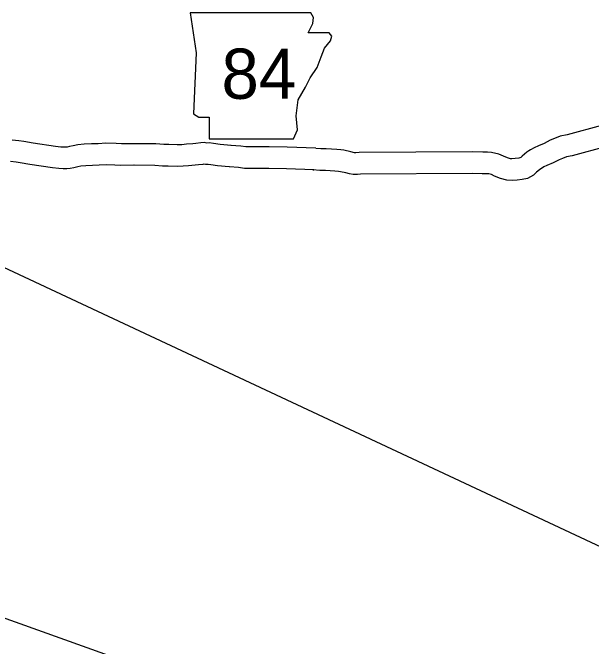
# Model space of a CAD drawing. Extents: x 1373862 to 1377080, y 1164775 to 1170415.
# Drawn here: x 1374204.1 to 1374284.4, y 1170151.1 to 1170239 of the extents above; entities that cross this region are included whole.
import ezdxf

# ---------------------------------------------------------------- set-up
doc = ezdxf.new("R2010")
doc.units = 0
doc.layers.add('1', color=7, linetype='Continuous')
doc.layers.add('Default', color=7, linetype='Continuous')

msp = doc.modelspace()

# ---------------------------------------------------------------- linework, layer by layer
at = {"layer": '1'}
for p in [(1374155.089, 1170226.036), (1374172.843, 1170165.768)]:
    msp.add_line(p, (1374640.758, 1169998.763), dxfattribs=at)
at = {"layer": 'Default'}
msp.add_lwpolyline([(1374228.721, 1170239.039), (1374229.559, 1170233.456), (1374229.186, 1170224.988), (1374229.931, 1170224.523), (1374231.327, 1170224.523), (1374231.327, 1170221.545), (1374243.051, 1170221.545), (1374243.609, 1170222.755), (1374243.423, 1170224.709), (1374243.702, 1170226.942), (1374244.725, 1170228.71), (1374245.377, 1170230.013), (1374246.307, 1170231.409), (1374246.866, 1170232.897), (1374247.331, 1170234.107), (1374248.168, 1170235.13), (1374248.354, 1170235.782), (1374247.982, 1170236.247), (1374245.098, 1170236.247), (1374245.749, 1170237.55), (1374245.842, 1170238.387), (1374245.456, 1170239.03)], close=True, dxfattribs=at)
for points in [[(1374285.752, 1170223.374), (1374281.025, 1170222.103), (1374280.056, 1170221.897), (1374279.255, 1170221.581), (1374278.653, 1170221.336), (1374277.813, 1170220.895), (1374277.029, 1170220.568), (1374276.41, 1170220.299), (1374275.925, 1170220.007), (1374275.712, 1170219.849), (1374275.414, 1170219.672), (1374274.767, 1170219.126), (1374274.567, 1170218.935), (1374274.46, 1170218.875), (1374274.293, 1170218.841), (1374273.808, 1170218.786), (1374273.346, 1170218.75), (1374273.144, 1170218.762), (1374272.747, 1170218.87), (1374272.156, 1170219.114), (1374271.525, 1170219.411), (1374270.513, 1170219.647), (1374269.947, 1170219.656), (1374269.312, 1170219.67), (1374267.893, 1170219.718), (1374252.159, 1170219.623), (1374251.706, 1170219.577), (1374251.605, 1170219.573), (1374251.51, 1170219.593), (1374250.992, 1170219.728), (1374250.05, 1170219.935), (1374249.606, 1170219.981), (1374249.067, 1170220.037), (1374248.306, 1170220.105), (1374247.564, 1170220.131), (1374246.858, 1170220.134), (1374246.152, 1170220.2)], [(1374220.886, 1170220.857), (1374219.194, 1170220.814), (1374218.442, 1170220.882), (1374216.999, 1170220.935), (1374215.93, 1170220.852), (1374215.035, 1170220.834), (1374214.008, 1170220.772), (1374213.121, 1170220.696), (1374212.473, 1170220.56), (1374211.992, 1170220.451), (1374211.656, 1170220.393), (1374211.42, 1170220.37), (1374211.122, 1170220.36), (1374210.747, 1170220.379), (1374210.041, 1170220.472), (1374206.93, 1170220.94), (1374205.634, 1170221.156), (1374204.962, 1170221.27), (1374204.011, 1170221.359)], [(1374234.401, 1170220.612), (1374232.857, 1170220.765), (1374231.948, 1170220.886), (1374231.353, 1170220.953), (1374231.042, 1170220.95), (1374230.675, 1170221.001), (1374230.205, 1170220.98), (1374229.501, 1170220.897), (1374229.074, 1170220.845), (1374228.205, 1170220.77), (1374227.534, 1170220.715), (1374226.904, 1170220.674), (1374225.757, 1170220.73), (1374225.041, 1170220.743), (1374223.952, 1170220.844), (1374220.931, 1170220.857)], [(1374246.152, 1170220.214), (1374242.151, 1170220.35), (1374239.667, 1170220.429), (1374238.089, 1170220.424), (1374236.455, 1170220.409), (1374235.751, 1170220.523), (1374234.352, 1170220.616)], [(1374286.479, 1170220.463), (1374281.727, 1170219.185), (1374280.923, 1170219.014), (1374280.371, 1170218.797), (1374279.919, 1170218.612), (1374279.09, 1170218.177), (1374278.204, 1170217.808), (1374277.788, 1170217.627), (1374277.598, 1170217.512), (1374277.375, 1170217.347), (1374277.157, 1170217.218), (1374276.774, 1170216.894), (1374276.36, 1170216.499), (1374275.514, 1170216.029), (1374274.765, 1170215.875), (1374274.092, 1170215.799), (1374273.378, 1170215.744), (1374272.661, 1170215.784), (1374271.777, 1170216.025), (1374270.944, 1170216.368), (1374270.533, 1170216.562), (1374270.144, 1170216.653), (1374269.892, 1170216.657), (1374269.229, 1170216.671), (1374267.852, 1170216.717), (1374252.322, 1170216.624), (1374251.917, 1170216.583), (1374251.341, 1170216.56), (1374250.815, 1170216.674), (1374250.292, 1170216.81), (1374249.574, 1170216.968), (1374249.298, 1170216.996), (1374248.778, 1170217.051), (1374248.12, 1170217.11), (1374247.505, 1170217.131), (1374246.713, 1170217.134), (1374245.711, 1170217.228), (1374245.875, 1170217.222)], [(1374243.437, 1170220.307), (1374243.404, 1170220.308)], [(1374220.962, 1170217.857), (1374219.096, 1170217.81), (1374218.251, 1170217.887), (1374217.06, 1170217.931), (1374216.076, 1170217.855), (1374215.155, 1170217.836), (1374214.228, 1170217.78), (1374213.56, 1170217.723), (1374213.112, 1170217.628), (1374212.578, 1170217.508), (1374212.058, 1170217.418), (1374211.616, 1170217.375), (1374211.096, 1170217.357), (1374210.473, 1170217.389), (1374209.621, 1170217.502), (1374206.46, 1170217.977), (1374205.138, 1170218.198), (1374204.572, 1170218.293), (1374203.767, 1170218.368)], [(1374234.105, 1170217.627), (1374232.512, 1170217.785), (1374231.582, 1170217.908), (1374231.197, 1170217.951), (1374230.849, 1170217.948), (1374230.536, 1170217.991), (1374230.448, 1170217.987), (1374229.856, 1170217.918), (1374229.385, 1170217.861), (1374228.458, 1170217.78), (1374227.753, 1170217.723), (1374226.927, 1170217.67), (1374225.657, 1170217.731), (1374224.875, 1170217.745), (1374223.806, 1170217.844), (1374220.918, 1170217.857)], [(1374245.875, 1170217.222), (1374242.053, 1170217.352), (1374239.624, 1170217.429), (1374238.107, 1170217.425), (1374236.227, 1170217.407), (1374235.412, 1170217.539), (1374234.154, 1170217.623)]]:
    msp.add_lwpolyline(points, dxfattribs=at)

# ---------------------------------------------------------------- texts
msp.add_text('84', height=6.9696, dxfattribs=at).set_placement((1374233.053, 1170227.083))

doc.saveas('drawing.dxf')
